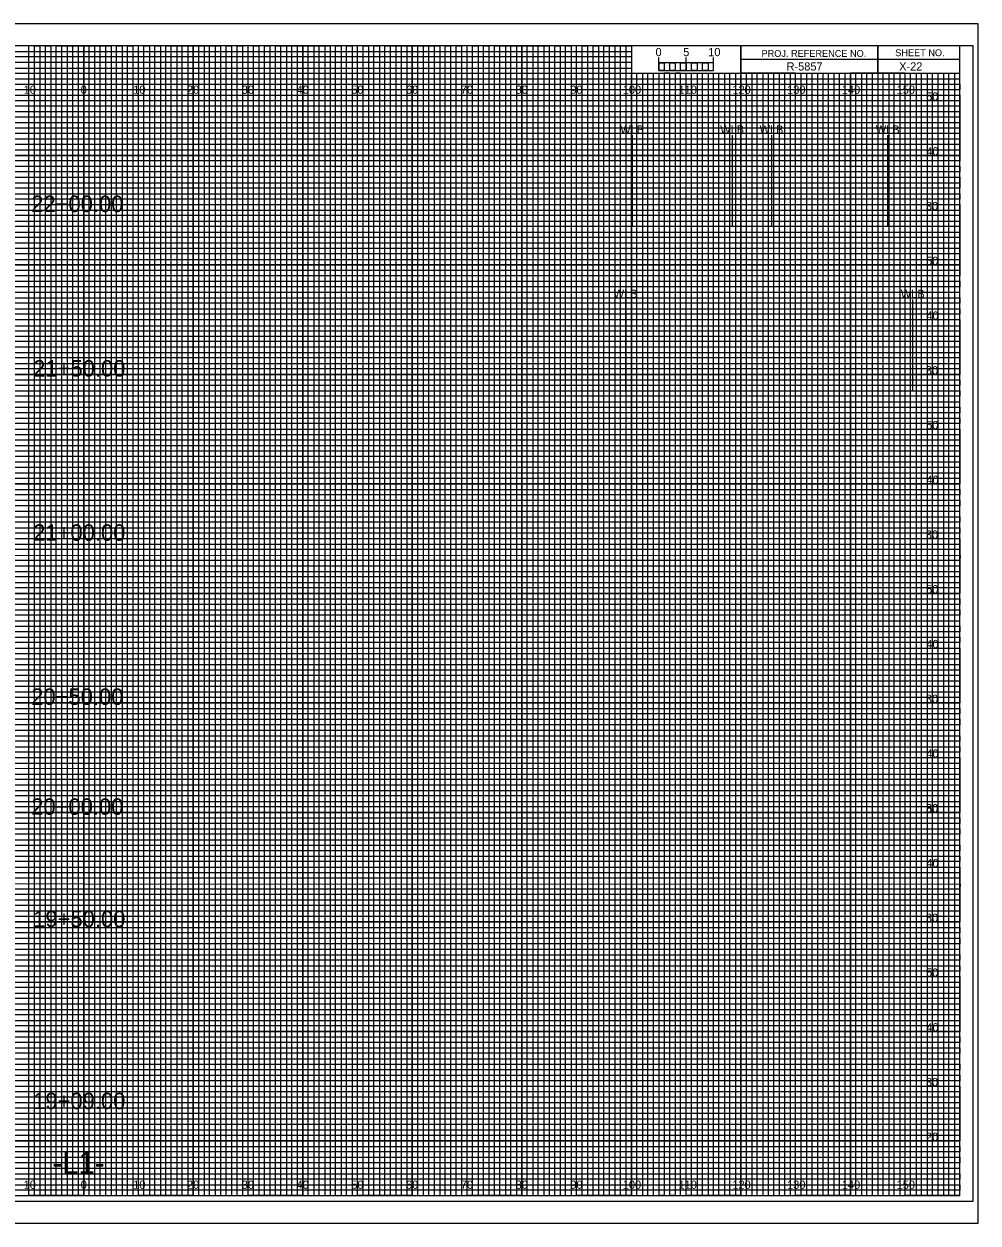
# Model space of a CAD drawing. Extents: x -13 to 323, y -5 to 214.
# Drawn here: x 149.1 to 323.3, y -5 to 214 of the extents above; entities that cross this region are included whole.
import ezdxf

# ---------------------------------------------------------------- set-up
doc = ezdxf.new("R2010")
doc.units = 0
for name, color, linetype in [('Default', 7, 'Continuous'), ('Exist Cross Section Cell', 7, 'Continuous'), ('Exist XS Center Line Elevation Label', 7, 'Continuous'), ('Exist XS Ground Line', 7, 'Continuous'), ('Prop CMT Pvmt Course 1', 7, 'Continuous'), ('Prop CMT Pvmt Course 1 Wedge', 7, 'Continuous'), ('Prop CMT Pvmt Course 2', 7, 'Continuous'), ('Prop CMT Pvmt Course 2 Wedge', 7, 'Continuous'), ('Prop CMT Pvmt Course 3', 7, 'Continuous'), ('Prop CMT Pvmt Surface', 7, 'Continuous'), ('Prop CMT Pvmt Surface Shoulder', 7, 'Continuous'), ('Prop CMT Pvmt Wedge Surface 1', 7, 'Continuous'), ('Prop CMT Shld Paved Course 1', 7, 'Continuous'), ('Prop CMT Shld Paved Course 2', 7, 'Continuous'), ('Prop CMT Shld Paved Course 3', 7, 'Continuous'), ('Prop CMT Slope Grass', 7, 'Continuous'), ('Prop CMT Subgrade Earthwork', 7, 'Continuous'), ('Scratch_Level_0', 7, 'Continuous')]:
    doc.layers.add(name, color=color, linetype=linetype)

msp = doc.modelspace()

# ---------------------------------------------------------------- linework, layer by layer
at = {"layer": 'Default'}
for p, q in [((260.2, 176.93), (260.2, 193.67)), ((278.46, 176.93), (278.46, 193.67)), ((285.64, 176.93), (285.64, 193.67)), ((306.85, 176.93), (306.85, 193.67)), ((259, 146.93), (259, 163.67)), ((311.42, 146.93), (311.42, 163.67))]:
    msp.add_line(p, q, dxfattribs=at)
at = {"layer": 'Exist XS Center Line Elevation Label'}
for points in [[(145, 0), (155, 0), (155, 210), (165, 210), (165, 0), (175, 0), (175, 210), (185, 210), (185, 0), (195, 0), (195, 210), (205, 210), (205, 0), (215, 0), (215, 210), (225, 210), (225, 0), (235, 0), (235, 210), (245, 210), (245, 0), (255, 0), (255, 210), (259.93, 210), (260, 210), (260, 205), (264.99, 205), (264.99, 0), (275, 0), (275, 205), (285, 205), (285, 0), (295, 0), (295, 205), (305, 205), (305, 0), (315, 0), (315, 205)], [(0, 205), (275, 205)], [(0, 185), (320, 185), (320, 195), (0, 195)], [(0, 165), (320, 165), (320, 175), (0, 175)], [(0, 145), (320, 145), (320, 155), (0, 155)], [(0, 125), (320, 125), (320, 135), (0, 135)], [(0, 105), (320, 105), (320, 115), (0, 115)], [(0, 85), (320, 85), (320, 95), (0, 95)], [(0, 65), (320, 65), (320, 75), (0, 75)], [(0, 45), (320, 45), (320, 55), (0, 55)], [(0, 25), (320, 25), (320, 35), (0, 35)], [(0, 5), (320, 5), (320, 15), (0, 15)]]:
    msp.add_lwpolyline(points, dxfattribs=at)
at = {"layer": 'Exist XS Ground Line'}
for p, q in [((150, 210), (140, 210)), ((150, 0), (150, 210)), ((170, 210), (160, 210)), ((160, 210), (160, 0)), ((170, 0), (170, 210)), ((190, 210), (180, 210)), ((180, 210), (180, 0)), ((190, 0), (190, 210)), ((210, 210), (200, 210)), ((200, 210), (200, 0)), ((210, 0), (210, 210)), ((230, 210), (220, 210)), ((220, 210), (220, 0)), ((230, 0), (230, 210)), ((250, 210), (240, 210)), ((240, 210), (240, 0)), ((250, 0), (250, 210)), ((260, 210), (260, 0)), ((270, 0), (270, 205)), ((290, 205), (280, 205)), ((280, 205), (280, 0)), ((290, 0), (290, 205)), ((310, 205), (300, 205)), ((300, 205), (300, 0)), ((310, 0), (310, 205)), ((160, 0), (150, 0)), ((180, 0), (170, 0)), ((200, 0), (190, 0)), ((220, 0), (210, 0)), ((240, 0), (230, 0)), ((260, 0), (250, 0)), ((280, 0), (270, 0)), ((300, 0), (290, 0)), ((320, 0), (310, 0)), ((320, 0), (320, 0))]:
    msp.add_line(p, q, dxfattribs=at)
for points in [[(0, 200), (320, 200), (320, 190), (0, 190)], [(0, 180), (320, 180), (320, 170), (0, 170)], [(0, 160), (320, 160), (320, 150), (0, 150)], [(0, 140), (320, 140), (320, 130), (0, 130)], [(0, 120), (320, 120), (320, 110), (0, 110)], [(0, 100), (320, 100), (320, 90), (0, 90)], [(0, 80), (320, 80), (320, 70), (0, 70)], [(0, 60), (320, 60), (320, 50), (0, 50)], [(0, 40), (320, 40), (320, 30), (0, 30)], [(0, 20), (320, 20), (320, 10), (0, 10)]]:
    msp.add_lwpolyline(points, dxfattribs=at)
at = {"layer": 'Prop CMT Pvmt Course 1'}
msp.add_lwpolyline([(-10.8, -1), (322.4, -1), (322.4, 210), (-10.8, 210)], close=True, dxfattribs=at)
at = {"layer": 'Prop CMT Pvmt Course 2'}
for p, q in [((150, 0), (150, 210)), ((160, 0), (160, 210)), ((170, 0), (170, 210)), ((180, 0), (180, 210)), ((190, 0), (190, 210)), ((200, 0), (200, 210)), ((210, 0), (210, 210)), ((220, 0), (220, 210)), ((230, 0), (230, 210)), ((240, 0), (240, 210)), ((250, 0), (250, 210)), ((260, 0), (260, 204.69)), ((270, 0), (270, 204.69)), ((280, 0), (280, 204.69)), ((290, 0), (290, 204.69)), ((300, 0), (300, 204.69)), ((310, 0), (310, 204.69)), ((0, 200), (320, 200)), ((0, 190), (320, 190)), ((0, 180), (320, 180)), ((0, 170), (320, 170)), ((0, 160), (320, 160)), ((0, 150), (320, 150)), ((0, 140), (320, 140)), ((0, 130), (320, 130)), ((0, 120), (320, 120)), ((0, 110), (320, 110)), ((0, 100), (320, 100)), ((0, 90), (320, 90)), ((0, 80), (320, 80)), ((0, 70), (320, 70)), ((0, 60), (320, 60)), ((0, 50), (320, 50)), ((0, 40), (320, 40)), ((0, 30), (320, 30)), ((0, 20), (320, 20)), ((0, 10), (320, 10))]:
    msp.add_line(p, q, dxfattribs=at)
at = {"layer": 'Prop CMT Pvmt Course 3'}
for p, q in [((323.3, 214), (-13.4, 214)), ((-13.4, -5), (323.3, -5))]:
    msp.add_line(p, q, dxfattribs=at)
at = {"layer": 'Prop CMT Shld Paved Course 1'}
for p, q in [((267, 205), (266.01, 205)), ((266.01, 205), (266.01, 0)), ((267, 0), (267, 205)), ((269, 205), (268, 205)), ((268, 205), (268, 0)), ((269, 0), (269, 205)), ((266.01, 0), (265, 0)), ((268, 0), (267, 0))]:
    msp.add_line(p, q, dxfattribs=at)
for points in [[(150, 0), (151, 0), (151, 210), (152, 210), (152, 0)], [(152, 0), (153, 0), (153, 210), (154, 210), (154, 0)], [(155, 0), (156, 0), (156, 210), (157, 210), (157, 0)], [(157, 0), (158, 0), (158, 210), (159, 210), (159, 0)], [(160, 0), (161, 0), (161, 210), (162, 210), (162, 0)], [(162, 0), (163, 0), (163, 210), (164, 210), (164, 0)], [(165, 0), (166, 0), (166, 210), (167, 210), (167, 0)], [(167, 0), (168, 0), (168, 210), (169, 210), (169, 0)], [(170, 0), (171, 0), (171, 210), (172, 210), (172, 0)], [(172, 0), (173, 0), (173, 210), (174, 210), (174, 0)], [(175, 0), (176, 0), (176, 210), (177, 210), (177, 0)], [(177, 0), (178, 0), (178, 210), (179, 210), (179, 0)], [(180, 0), (181, 0), (181, 210), (182, 210), (182, 0)], [(182, 0), (183, 0), (183, 210), (184, 210), (184, 0)], [(185, 0), (186, 0), (186, 210), (187, 210), (187, 0)], [(187, 0), (188, 0), (188, 210), (189, 210), (189, 0)], [(190, 0), (191, 0), (191, 210), (192, 210), (192, 0)], [(192, 0), (193, 0), (193, 210), (194, 210), (194, 0)], [(195, 0), (196, 0), (196, 210), (197, 210), (197, 0)], [(197, 0), (198, 0), (198, 210), (199, 210), (199, 0)], [(200, 0), (201, 0), (201, 210), (202, 210), (202, 0)], [(202, 0), (203, 0), (203, 210), (204, 210), (204, 0)], [(205, 0), (206, 0), (206, 210), (207, 210), (207, 0)], [(207, 0), (208, 0), (208, 210), (209, 210), (209, 0)], [(210, 0), (211, 0), (211, 210), (212, 210), (212, 0)], [(212, 0), (213, 0), (213, 210), (214, 210), (214, 0)], [(215, 0), (216, 0), (216, 210), (217, 210), (217, 0)], [(217, 0), (218, 0), (218, 210), (219, 210), (219, 0)], [(220, 0), (221, 0), (221, 210), (222, 210), (222, 0)], [(222, 0), (223, 0), (223, 210), (224, 210), (224, 0)], [(225, 0), (226, 0), (226, 210), (227, 210), (227, 0)], [(227, 0), (228, 0), (228, 210), (229, 210), (229, 0)], [(230, 0), (231, 0), (231, 210), (232, 210), (232, 0)], [(232, 0), (233, 0), (233, 210), (234, 210), (234, 0)], [(235, 0), (236, 0), (236, 210), (237, 210), (237, 0)], [(237, 0), (238, 0), (238, 210), (239, 210), (239, 0)], [(240, 0), (241, 0), (241, 210), (242, 210), (242, 0)], [(242, 0), (243, 0), (243, 210), (244, 210), (244, 0)], [(245, 0), (246, 0), (246, 210), (247, 210), (247, 0)], [(247, 0), (248, 0), (248, 210), (249, 210), (249, 0)], [(250, 0), (251, 0), (251, 210), (252, 210), (252, 0)], [(252, 0), (253, 0), (253, 210), (254, 210), (254, 0)], [(255, 0), (256, 0), (256, 210), (257, 210), (257, 0)], [(257, 0), (258, 0), (258, 210), (259, 210), (259, 0)], [(260, 0), (261, 0), (261, 205), (262.02, 205), (262.02, 0)], [(262, 0), (263, 0), (263, 205), (263.99, 205), (263.99, 0)], [(270, 0), (270.98, 0), (270.98, 205), (272, 205), (272, 0)], [(272, 0), (273, 0), (273, 205), (274.05, 205), (274.05, 0)], [(275, 0), (276, 0), (276, 205), (277, 205), (277, 0)], [(277, 0), (278, 0), (278, 205), (279, 205), (279, 0)], [(280, 0), (281, 0), (281, 205), (282, 205), (282, 0)], [(282, 0), (283, 0), (283, 205), (284, 205), (284, 0)], [(285, 0), (286, 0), (286, 205), (287, 205), (287, 0)], [(287, 0), (288, 0), (288, 205), (289, 205), (289, 0)], [(290, 0), (291, 0), (291, 205), (292, 205), (292, 0)], [(292, 0), (293, 0), (293, 205), (294, 205), (294, 0)], [(295, 0), (296, 0), (296, 205), (297, 205), (297, 0)], [(297, 0), (298, 0), (298, 205), (299, 205), (299, 0)], [(300, 0), (301, 0), (301, 205), (302, 205), (302, 0)], [(302, 0), (303, 0), (303, 205), (304, 205), (304, 0)], [(305, 0), (306, 0), (306, 205), (307, 205), (307, 0)], [(307, 0), (308, 0), (308, 205), (309, 205), (309, 0)], [(310, 0), (311, 0), (311, 205), (312, 205), (312, 0)], [(312, 0), (313, 0), (313, 205), (314, 205), (314, 0)], [(315, 0), (316, 0), (316, 205), (317, 205), (317, 0)], [(317, 0), (318, 0), (318, 205), (319, 205), (319, 0)]]:
    msp.add_lwpolyline(points, dxfattribs=at)
at = {"layer": 'Prop CMT Shld Paved Course 2'}
for p, q in [((265, 205.49), (265, 207.9)), ((265, 206.9), (265, 207.9)), ((270, 205.49), (270, 207.9)), ((275, 205.49), (275, 207.9)), ((275, 206.9), (275, 207.9))]:
    msp.add_line(p, q, dxfattribs=at)
for points in [[(275, 206.9), (265, 206.9), (265, 205.49), (275, 205.49)], [(265, 206.9), (266, 206.9), (266, 205.49), (265, 205.49)], [(267, 206.9), (268, 206.9), (268, 205.49), (267, 205.49)], [(269, 206.9), (270, 206.9), (270, 205.49), (269, 205.49)], [(271, 206.9), (272, 206.9), (272, 205.49), (271, 205.49)], [(273, 206.9), (274, 206.9), (274, 205.49), (273, 205.49)]]:
    msp.add_lwpolyline(points, close=True, dxfattribs=at)
at = {"layer": 'Prop CMT Shld Paved Course 3'}
msp.add_lwpolyline([(-13.4, -5), (323.3, -5), (323.3, 214), (-13.4, 214)], close=True, dxfattribs=at)
at = {"layer": 'Prop CMT Slope Grass'}
for p, q in [((305, 210), (305, 205)), ((305, 205), (305, 210)), ((280, 207.5), (280, 205)), ((320, 207.49), (280, 207.49)), ((280, 205), (320, 205))]:
    msp.add_line(p, q, dxfattribs=at)
for points in [[(320, 210), (0, 210), (0, 0), (320, 0)], [(280, 210), (260, 210), (260, 205.03), (280, 205.03)], [(320, 210), (280, 210), (280, 205), (320, 205)]]:
    msp.add_lwpolyline(points, close=True, dxfattribs=at)
at = {"layer": 'Scratch_Level_0'}
for p, q in [((0, 209), (260, 209)), ((260, 209), (260, 207.98)), ((260, 207.98), (0, 207.98)), ((0, 207), (260, 207)), ((260, 205.89), (0, 205.89)), ((260, 207), (260, 205.89)), ((0, 204), (320, 204))]:
    msp.add_line(p, q, dxfattribs=at)
for points in [[(0, 203), (270, 203), (320, 203), (320, 202), (0, 202)], [(0, 201), (320, 201), (320, 199), (0, 199)], [(0, 198), (320, 198), (320, 197), (0, 196.98)], [(0, 196), (320, 196), (320, 194), (0, 194)], [(0, 193), (320, 193), (320, 192), (0, 192)], [(0, 191), (320, 191), (320, 189), (0, 189)], [(0, 188), (320, 188), (320, 187), (0, 187)], [(0, 186), (320, 186), (320, 184), (0, 184)], [(0, 183), (320, 183), (320, 182), (0, 182)], [(0, 181), (320, 181), (320, 179), (0, 179)], [(0, 178), (320, 178), (320, 177), (0, 177)], [(0, 176), (320, 176), (320, 173.95), (320, 173), (320, 172), (0, 172)], [(0, 174), (320, 174), (320, 173), (0, 173)], [(0, 171), (320, 171), (320, 169), (0, 169.03)], [(0, 169.03), (320, 169), (320, 168), (0, 168)], [(0, 167), (320, 167), (320, 166), (0, 166)], [(0, 164), (320, 164), (320, 163), (0, 163)], [(0, 162), (320, 162), (320, 161), (0, 161)], [(-0.07, 158.89), (320, 158.89), (320, 157.88), (-0.07, 157.88)], [(0, 157), (320, 157), (320, 156), (0, 156)], [(0, 154), (320, 154), (320, 153), (0, 153)], [(0, 152), (320, 152), (320, 151), (0, 151)], [(0, 149), (320, 149), (320, 148), (0, 148)], [(0, 147), (320, 147), (320, 146), (0, 146)], [(0, 144), (320, 144), (320, 143), (0, 143)], [(0, 142), (320, 142), (320, 141), (0, 141)], [(0, 139), (320, 139), (319.99, 137.98), (0, 138)], [(0, 137), (320, 137), (320, 136), (0, 136)], [(0, 134), (320, 134), (320, 133), (0, 133)], [(0, 132), (320, 132), (320, 131), (0, 131)], [(0, 129), (320, 129), (320, 128), (0, 128)], [(0, 127), (320, 127), (320, 126), (0, 126)], [(0, 124), (320, 124), (320, 123), (0, 123)], [(0, 122), (320, 122), (320, 121), (0, 121)], [(0, 119), (320, 119), (320, 118), (0, 118)], [(0, 116.99), (320.07, 116.91), (320, 116), (0, 116)], [(0, 114), (320, 114), (320, 113), (0, 113)], [(0, 112), (320, 112), (320, 111), (0, 111)], [(0, 109), (320, 109), (320, 108), (0, 108)], [(0, 107), (320, 107), (320, 106), (0, 106)], [(0, 104), (320, 104), (320, 103), (0, 103)], [(0, 102), (320, 102), (320, 101), (0, 101)], [(0, 99), (320, 99), (320, 98), (0, 98)], [(0, 97), (320, 97), (320, 96), (0, 96)], [(0, 94), (320, 94), (320, 93), (0, 93)], [(0, 92), (320, 92), (320, 91), (0, 91)], [(0, 89), (320, 89), (320, 88), (0, 88)], [(0, 87), (320, 87), (320, 86), (0, 86)], [(0, 84), (320, 84), (320, 83), (0, 83)], [(0, 82), (320, 82), (320, 81), (0, 81)], [(0, 79), (320, 79), (319.99, 77.98), (0, 78)], [(0, 77), (320, 77), (320, 76), (0, 76)], [(0, 74), (320, 74), (320, 73), (0, 73)], [(0, 72), (320, 72), (320, 71), (0, 71)], [(0, 69), (320, 69), (320, 68), (0, 68)], [(0, 67), (320, 67), (320, 66), (0, 66)], [(0, 64), (320, 64), (320, 63), (0, 63)], [(0, 62), (320, 62), (320, 61), (0, 61)], [(0, 59), (320, 59), (320, 58), (0, 58)], [(0, 56.99), (320.07, 56.91), (320, 56), (0, 56)], [(0, 54), (320, 54), (320, 53), (0, 53)], [(0, 52), (320, 52), (320, 51), (0, 51)], [(0, 49), (320, 49), (320, 48), (0, 48)], [(0, 47), (320, 47), (320, 46), (0, 46)], [(0, 44), (320, 44), (320, 43), (0, 43)], [(0, 42), (320, 42), (320, 41), (0, 41)], [(0, 39), (320, 39), (320, 38), (0, 38)], [(0, 37), (320, 37), (320, 36), (0, 36)], [(0, 34), (320, 34), (320, 33), (0, 33)], [(0, 32), (320, 32), (320, 31), (0, 31)], [(0, 29), (320, 29), (320, 28), (0, 28)], [(0, 27), (320, 27), (320, 26), (0, 26)], [(0, 24), (320, 24), (320, 23), (0, 23)], [(0, 22), (320, 22), (320, 21), (0, 21)], [(0, 19), (320, 19), (320, 18), (0, 18)], [(0, 17), (320, 17), (320, 16), (0, 16)], [(0, 14), (320, 14), (320, 13), (0, 13)], [(0, 12), (320, 12), (320, 11), (0, 11)], [(0, 9), (320, 9), (320, 8), (0, 8)], [(0, 7), (320, 7), (320, 6), (0, 6)], [(0, 4), (320, 4), (320, 3), (0, 3)], [(0, 2), (320, 2), (320, 1), (0, 1)]]:
    msp.add_lwpolyline(points, dxfattribs=at)

# ---------------------------------------------------------------- texts
at = {"layer": 'Default'}
for p in [(257.98, 193.97), (276.24, 193.97), (283.42, 193.97), (304.63, 193.97), (256.77, 163.97), (309.2, 163.97)]:
    msp.add_text('WLB', height=1.5, dxfattribs=at).set_placement(p)
at = {"layer": 'Exist Cross Section Cell'}
for s, p in [('10', (149.04, 201.25)), ('0', (159.45, 201.25)), ('0', (159.45, 201.25)), ('10', (169.04, 201.25)), ('20', (178.86, 201.25)), ('30', (188.86, 201.25)), ('40', (198.86, 201.25)), ('50', (208.86, 201.25)), ('60', (218.86, 201.25)), ('70', (228.86, 201.25)), ('80', (238.86, 201.25)), ('90', (248.86, 201.25)), ('100', (258.44, 201.25)), ('110', (268.62, 201.25)), ('120', (278.44, 201.25)), ('130', (288.44, 201.25)), ('140', (298.44, 201.25)), ('150', (308.44, 201.25)), ('10', (149.04, 1.25)), ('0', (159.45, 1.25)), ('0', (159.45, 1.25)), ('10', (169.04, 1.25)), ('20', (178.86, 1.25)), ('30', (188.86, 1.25)), ('40', (198.86, 1.25)), ('50', (208.86, 1.25)), ('60', (218.86, 1.25)), ('70', (228.86, 1.25)), ('80', (238.86, 1.25)), ('90', (248.86, 1.25)), ('100', (258.44, 1.25)), ('110', (268.62, 1.25)), ('120', (278.44, 1.25)), ('130', (288.44, 1.25)), ('140', (298.44, 1.25)), ('150', (308.44, 1.25))]:
    msp.add_text(s, height=1.5, dxfattribs=at).set_placement(p)
at = {"layer": 'Prop CMT Pvmt Course 1 Wedge'}
msp.add_text('R-5857', height=1.5, dxfattribs=at).set_placement((288.34, 205.5))
at = {"layer": 'Prop CMT Pvmt Course 2 Wedge'}
msp.add_text('-L1-', height=4, dxfattribs=at).set_placement((154.28, 4))
at = {"layer": 'Prop CMT Pvmt Surface'}
msp.add_text('X-22', height=1.5, dxfattribs=at).set_placement((308.9, 205.5))
at = {"layer": 'Prop CMT Pvmt Surface Shoulder'}
for s, p in [('22+00.00', (150.41, 179.65)), ('21+50.00', (150.77, 149.6)), ('21+00.00', (150.77, 119.61)), ('20+50.00', (150.41, 89.64)), ('20+00.00', (150.41, 69.56)), ('19+50.00', (150.77, 49.05)), ('19+09.00', (150.77, 15.8))]:
    msp.add_text(s, height=3, dxfattribs=at).set_placement(p)
at = {"layer": 'Prop CMT Pvmt Wedge Surface 1'}
for s, p in [('5', (269.47, 208.12)), ('10', (274.04, 208.12))]:
    msp.add_text(s, height=1.5, dxfattribs=at).set_placement(p)
at = {"layer": 'Prop CMT Shld Paved Course 2'}
msp.add_text('0', height=1.5, dxfattribs=at).set_placement((264.41, 208.12))
at = {"layer": 'Prop CMT Slope Grass'}
for s, p in [('PROJ. REFERENCE NO.', (283.77, 207.99)), ('SHEET NO.', (308.19, 208.12))]:
    msp.add_text(s, height=1.25, dxfattribs=at).set_placement(p)
at = {"layer": 'Prop CMT Subgrade Earthwork'}
for s, p in [('50', (313.82, 200)), ('40', (313.87, 190)), ('30', (313.78, 180)), ('50', (313.82, 170)), ('40', (313.87, 160)), ('30', (313.78, 150)), ('50', (313.82, 140)), ('40', (313.87, 130)), ('30', (313.78, 120)), ('50', (313.82, 110)), ('40', (313.87, 100)), ('30', (313.78, 90)), ('40', (313.87, 80)), ('30', (313.78, 70)), ('50', (313.82, 70)), ('40', (313.87, 60)), ('30', (313.78, 50)), ('50', (313.82, 40)), ('40', (313.87, 30)), ('30', (313.78, 20)), ('20', (313.8, 10))]:
    msp.add_text(s, height=1.5, dxfattribs=at).set_placement(p)

doc.saveas('drawing.dxf')
